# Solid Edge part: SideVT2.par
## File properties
Author: harmonj5
Template: ansi part.par
Last saved by: harmonj5
Revision: 7
Application: Solid Edge
Accuracy: 0.990
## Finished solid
Body 1: solid body, 70 faces, 198 edges, 132 vertices, 2 separate solids.
  Faces by surface: plane 42, cylinder 19, swept 9
  Edges by curve: line 142, circle 38, spline 18
Bounding box of the edges (mm; curved faces can reach further): 187.481 x 22.561 x 3.175, from (-219.7328, 16.3246, -3.175) to (-32.2514, 38.8855, 0).
Cylindrical faces by radius (mm): R1.5875 x1, R3.175 x10, R9.0946 x1, R9.2633 x1, R13.294 x1, R171.5506 x1, R186.0532 x1, R221.2846 x1, R375.7977 x1, R1016.1542 x1
Planar faces by outward normal: +x 11, +y 5, +z 2, -x 6, -y 5, -z 2, oblique 11
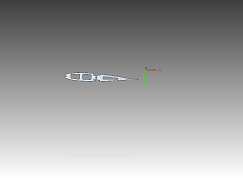
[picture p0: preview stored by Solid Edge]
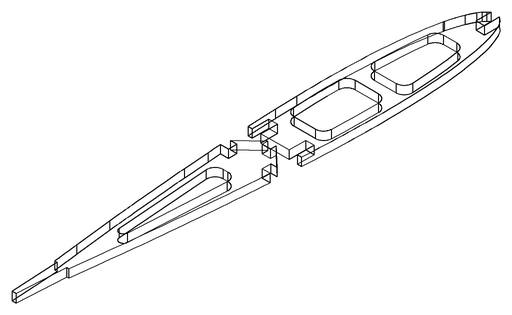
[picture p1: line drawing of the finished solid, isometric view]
